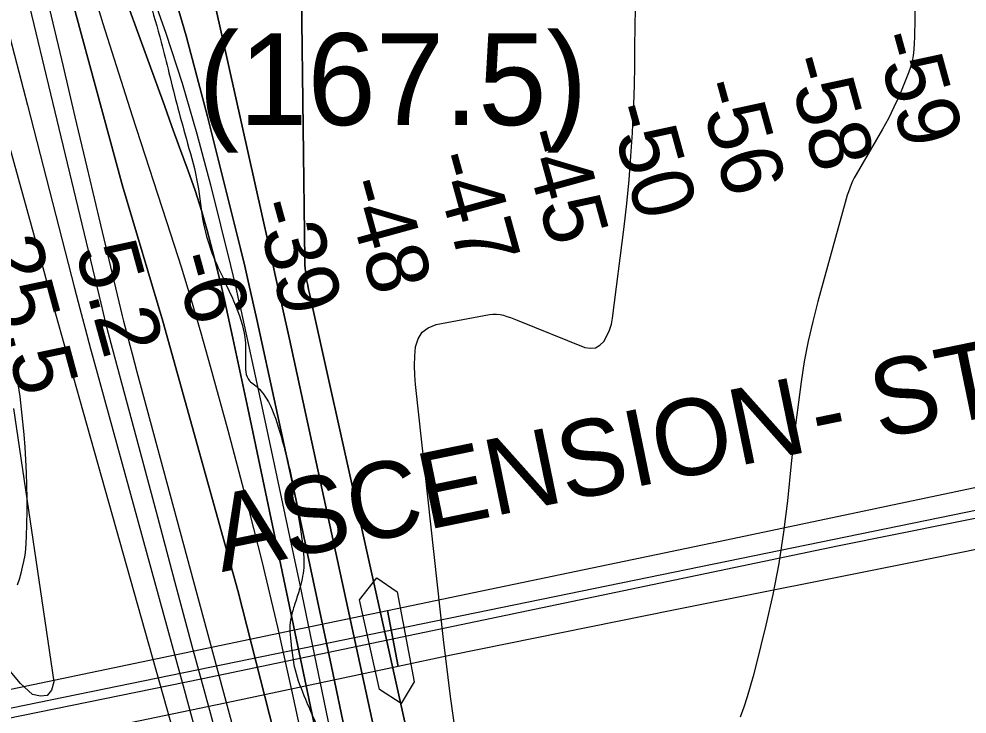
# Model space of a CAD drawing. Extents: x 3405885 to 3443815, y 558517 to 583997.
# Drawn here: x 3412709 to 3413741, y 581101 to 581858 of the extents above; entities that cross this region are included whole.
import ezdxf

# ---------------------------------------------------------------- set-up
doc = ezdxf.new("R2010")
doc.units = 0
for name, color, linetype in [('V-BRDG-IDEN', 7, 'Continuous'), ('V-BRDG-OTLN', 7, 'Continuous'), ('V-CHAN-DOCK', 7, 'Continuous'), ('V-CHAN-NAID', 7, 'Continuous'), ('V-RIVR-EDGE', 7, 'Continuous'), ('V-RIVR-RANG', 7, 'Continuous'), ('V-ROAD-CNTR', 7, 'Continuous'), ('V-TOPO-DPTH', 7, 'Continuous'), ('V-TOPO-MAJR', 7, 'Continuous'), ('V-TOPO-MINR', 7, 'Continuous'), ('V-TOPO-WATR', 7, 'Continuous')]:
    doc.layers.add(name, color=color, linetype=linetype)

msp = doc.modelspace()

# ---------------------------------------------------------------- linework, layer by layer
at = {"layer": 'V-BRDG-OTLN'}
for points in [[(3417680.4, 582119.8), (3417601.8, 582104.6), (3417266, 582031.9), (3417072.3, 581991.6), (3416368.4, 581849.5), (3415729.2, 581717.9), (3415183.5, 581606.5), (3414289.2, 581422.5), (3413599.8, 581283.7), (3412908.9, 581139.2), (3412266.4, 581008.4), (3412181.4, 580990.5), (3412075.2, 580969.3), (3411951.8, 580944.2), (3411795.1, 580912.3), (3411642, 580880.6), (3411498.5, 580851.2), (3411034.3, 580756.7), (3410912.4, 580731.2)], [(3411677.7, 580918.3), (3412408.2, 581067.1), (3413000.1, 581190.8), (3413110.1, 581213.7), (3413121.5, 581152.9), (3412941.9, 581114.8), (3412765.6, 581078.1), (3412568.7, 581037.8), (3412280.7, 580978.9), (3411914.4, 580903.8)]]:
    msp.add_lwpolyline(points, dxfattribs=at)
msp.add_lwpolyline([(3413110.1, 581213.7), (3413479, 581290.8), (3413890.7, 581377.6), (3413902.9, 581311.2), (3413681.3, 581266.1), (3413421.4, 581214.2), (3413179.2, 581165.2), (3413121.5, 581152.9)], close=True, dxfattribs=at)
at = {"layer": 'V-CHAN-DOCK'}
msp.add_lwpolyline([(3413101.3, 581127.9), (3413079.4, 581225.3), (3413098.4, 581249.5), (3413120.6, 581234), (3413139, 581136), (3413124.9, 581112.4)], close=True, dxfattribs=at)
at = {"layer": 'V-RIVR-EDGE'}
msp.add_spline([(3412820.9, 582098.3), (3412817.8, 582058), (3412815.6, 582029.5), (3412817.7, 582007.9), (3412825.7, 581980.1), (3412850.3, 581879.9), (3412863.7, 581832.7), (3412872, 581799.1), (3412892.3, 581722.3), (3412903.2, 581678.4), (3412909.6, 581634.8), (3412920.5, 581599), (3412934, 581569.3), (3412943.4, 581548.5), (3412954.7, 581511.2), (3412955.3, 581484.9), (3412959.7, 581464), (3412965.1, 581459.6), (3412977.9, 581445), (3412992.4, 581409.1), (3413006.5, 581353.1), (3413015.2, 581302.3), (3413018.7, 581260.3), (3413013.9, 581236.1), (3413008.8, 581220.1), (3413005.1, 581206.5), (3413003.6, 581194.5), (3413004.7, 581180.2), (3413009.3, 581149.1), (3413020.6, 581117.3), (3413042, 581073), (3413073, 581031.3), (3413081, 581018.1), (3413088.7, 580999.8), (3413094.4, 580977.9), (3413100.2, 580939.1), (3413102.7, 580912), (3413106.3, 580894.1), (3413113.5, 580861.9), (3413124.8, 580824.3), (3413140, 580781.4), (3413146.5, 580756.9), (3413148.7, 580740.1), (3413153.8, 580721.8), (3413161, 580692.6), (3413184.2, 580615.7), (3413194, 580582.5), (3413204.2, 580568.2), (3413207.8, 580561.6), (3413214, 580535.3), (3413232.1, 580461.7), (3413244, 580397.7), (3413253, 580345.1), (3413251.9, 580330.8), (3413256.4, 580258.4), (3413262.5, 580217.5), (3413264.6, 580175.4), (3413271.5, 580146.5), (3413278.7, 580117.3), (3413280.2, 580104.8), (3413276.4, 580060.6), (3413276.3, 580025.9), (3413275.6, 580012.4), (3413275.5, 580006.1), (3413277.7, 580003.2), (3413288, 580000.6), (3413298.6, 579998.4), (3413303.7, 579992.2), (3413305.5, 579985.2), (3413310.1, 579953.8), (3413314.5, 579931.1), (3413321, 579914.6), (3413327.2, 579894.5), (3413327.1, 579868.9), (3413323.4, 579842.6), (3413317.9, 579835.3), (3413316, 579824.7), (3413315.6, 579806.5), (3413320, 579780.1), (3413328, 579765.1), (3413335.6, 579758.2), (3413338.2, 579753.4), (3413338.9, 579747.5), (3413338.9, 579742.8), (3413335.5, 579730.7), (3413330.8, 579723.1), (3413327.8, 579714.3), (3413325.2, 579701.2), (3413326.7, 579689.5), (3413332.1, 579675.9), (3413338.3, 579668.2), (3413342.7, 579666.4), (3413352.6, 579666.7), (3413357.3, 579663.4), (3413365.3, 579652.4), (3413371.9, 579635.2), (3413374.8, 579618.4), (3413377.6, 579592.5), (3413379.4, 579557.4), (3413373.8, 579521.6), (3413375.2, 579501.1), (3413382.1, 579476.9), (3413395.1, 579440), (3413408.6, 579400.8), (3413417.6, 579358.8), (3413445.2, 579297.7), (3413449.9, 579271.7), (3413449.8, 579233.3), (3413439.5, 579191.3), (3413438.7, 579182.2), (3413439.8, 579172.7), (3413446, 579161.7), (3413464.9, 579134.6), (3413487.5, 579101.6), (3413497, 579074.9), (3413502.7, 579046.4), (3413506.7, 579018.2), (3413510.6, 578990.8), (3413518.6, 578952.4), (3413529.8, 578903.8), (3413538.1, 578871.6), (3413547.9, 578834.6), (3413558.4, 578787.4), (3413566.7, 578743.2), (3413574.6, 578699.3), (3413585.1, 578637.1), (3413595.2, 578577.2), (3413599.5, 578547.5), (3413610.7, 578516.1), (3413620.2, 578504), (3413626, 578499.2), (3413635.5, 578497), (3413635.9, 578494.4), (3413634.1, 578490.1), (3413632.2, 578487.1), (3413632.2, 578479.5), (3413633.2, 578455), (3413642.2, 578391), (3413644.3, 578359.2), (3413649, 578338.7), (3413656.3, 578322.2), (3413667.6, 578313.8), (3413676, 578309), (3413684.4, 578305.3), (3413688.8, 578300.2), (3413697.9, 578288.5), (3413702.2, 578272.4), (3413709.1, 578250.8), (3413714.9, 578233.2), (3413728.7, 578187.2), (3413734.8, 578151.3), (3413738.8, 578114.4), (3413740.5, 578084), (3413746.7, 578059.2), (3413750.7, 578043.4), (3413751.3, 578020), (3413747.6, 577990.8), (3413742, 577955), (3413736.9, 577934.5), (3413735.4, 577919.6), (3413733.5, 577904.2), (3413737.1, 577880.1), (3413741.4, 577864.7), (3413741.4, 577863.2), (3413750.2, 577865.8), (3413755, 577862.8), (3413760, 577845.7), (3413773.8, 577798.1), (3413781.8, 577765.2), (3413793, 577724.9), (3413797, 577700.4), (3413803.4, 577637.2), (3413804.4, 577613.8), (3413807.7, 577591.8), (3413815.3, 577561.1), (3413829.4, 577524.9), (3413841.8, 577493.8), (3413853.8, 577466), (3413863.2, 577445.5), (3413869.8, 577431.2), (3413869.8, 577426.1), (3413869.7, 577412.9), (3413868.9, 577389.5), (3413869.2, 577353), (3413871, 577339.8), (3413873.9, 577328.5), (3413883, 577306.5), (3413889.5, 577287.9), (3413905.1, 577244.3), (3413913.5, 577211), (3413925.4, 577161.3), (3413947.6, 577101.7), (3413958.8, 577073.5), (3413969, 577057.4), (3413973, 577043.8), (3413979.9, 577014.6), (3414002, 576930.8), (3414004.5, 576907.4), (3414006.3, 576897.2), (3414015, 576880.3), (3414024.5, 576858.8), (3414031.3, 576835.7), (3414040.8, 576799.5), (3414054.2, 576750.1), (3414062.5, 576713.9), (3414069.3, 576679.9), (3414074.4, 576668.5), (3414075.1, 576663.4), (3414103.1, 576586.2), (3414107.4, 576564.6), (3414115.4, 576529.2), (3414119, 576508), (3414142.2, 576433.7), (3414153.5, 576399.3), (3414159.6, 576378.5), (3414164.7, 576348.8), (3414174.1, 576303.8), (3414178, 576275), (3414184.1, 576248.3), (3414191.1, 576234), (3414204.1, 576202.1), (3414212.1, 576179.5), (3414243, 576089.5), (3414264.8, 576025.4), (3414269.5, 576005.7), (3414269.4, 575994.4), (3414267.6, 575989.1)], degree=3, dxfattribs=at)
at = {"layer": 'V-ROAD-CNTR'}
for points in [[(3409957, 580546.7), (3410940.8, 580747.1), (3417648.2, 582122.8)], [(3412707.2, 581241.7), (3412709.2, 581248), (3412711.1, 581254.4), (3412712.7, 581260.8), (3412714.1, 581267.3), (3412715.3, 581273.9), (3412716.3, 581280.4), (3412716.9, 581294.3), (3412717.3, 581308.2), (3412717.5, 581322.1), (3412717.5, 581336), (3412717.2, 581349.9), (3412716.8, 581363.8), (3412716.2, 581377.7), (3412715.3, 581391.6), (3412714.3, 581405.5), (3412713, 581419.3), (3412711.5, 581433.1), (3412709.9, 581446.9), (3412708, 581460.7)]]:
    msp.add_lwpolyline(points, dxfattribs=at)
at = {"layer": 'V-TOPO-DPTH'}
for points in [[(3412664.9, 582099.7), (3412797.7, 581548.5), (3412800.3, 581537.6), (3412803.1, 581526.7), (3412805.9, 581515.8), (3412808.7, 581505), (3412840.5, 581386.1), (3412859.4, 581315.8), (3412878.2, 581245.6), (3412897.1, 581175.3), (3412916, 581105.1), (3413003.6, 580780.3), (3413008.8, 580760.2), (3413013.8, 580740), (3413018.5, 580719.7), (3413022.9, 580699.3), (3413044.7, 580594.5), (3413059.4, 580521.5), (3413073.5, 580448.5), (3413086.5, 580375.3), (3413098.9, 580302), (3413146, 580011.8)], [(3412709.1, 582099.9), (3412741.1, 581971.9), (3412821.3, 581676.2), (3412865.2, 581528.8), (3412947.1, 581235.7), (3413065.1, 580772.3), (3413068.5, 580759.5), (3413070.2, 580745.9), (3413113.8, 580487.8), (3413186.9, 580114.7)], [(3413186.9, 580114.7), (3413113.8, 580487.8), (3413070.2, 580745.9), (3413068.5, 580759.5), (3413065.1, 580772.3), (3412947.1, 581235.7), (3412865.2, 581528.8), (3412821.3, 581676.2), (3412741.1, 581971.9), (3412709.1, 582099.9)], [(3413068.7, 581058.9), (3413049.1, 581152.8), (3413029.2, 581246.6), (3413009.1, 581340.4), (3412967.8, 581530.6), (3412963.5, 581550), (3412959.1, 581569.3), (3412954.5, 581588.7), (3412949.8, 581608), (3412914.1, 581751.8), (3412890.7, 581839.5), (3412865.3, 581926.6), (3412836.8, 582012.7), (3412806.3, 582098.2), (3412805.6, 582100.3)], [(3412805.6, 582100.3), (3412806.3, 582098.2), (3412836.8, 582012.7), (3412865.3, 581926.6), (3412890.7, 581839.5), (3412914.1, 581751.8), (3412949.8, 581608), (3412954.5, 581588.7), (3412959.1, 581569.3), (3412963.5, 581550), (3412967.8, 581530.6), (3413009.1, 581340.4), (3413029.2, 581246.6), (3413049.1, 581152.8), (3413068.7, 581058.9)], [(3412871.6, 582100.6), (3413021, 582101.1), (3413019.1, 582062.1), (3413017.1, 582003), (3413016.4, 581943.8), (3413016.5, 581884.6), (3413019.9, 581595.1), (3413020.1, 581590.5), (3413020.4, 581586), (3413020.9, 581581.4), (3413021.5, 581576.9), (3413022.3, 581572.4), (3413023.2, 581567.9), (3413024.1, 581563.4), (3413025.1, 581558.9), (3413187.4, 580829.4)], [(3413254.4, 580247.2), (3413244.5, 580301.5), (3413234.8, 580355.8), (3413163.6, 580759.6), (3413161.1, 580773.6), (3413158.5, 580787.6), (3413155.9, 580801.6), (3413153.2, 580815.6), (3413150.4, 580829.5), (3413147.6, 580843.5), (3413144.7, 580857.4), (3413141.7, 580871.3), (3413003.1, 581509.2), (3412995.7, 581543.2), (3412988.2, 581577.3), (3412980.7, 581611.3), (3412973.1, 581645.3), (3412871.6, 582100.6)], [(3413254.4, 580247.2), (3413244.5, 580301.5), (3413234.8, 580355.8), (3413163.6, 580759.6), (3413161.1, 580773.6), (3413158.5, 580787.6), (3413155.9, 580801.6), (3413153.2, 580815.6), (3413150.4, 580829.5), (3413147.6, 580843.5), (3413144.7, 580857.4), (3413141.7, 580871.3), (3413003.1, 581509.2), (3412995.7, 581543.2), (3412988.2, 581577.3), (3412980.7, 581611.3), (3412973.1, 581645.3), (3412871.6, 582100.6)], [(3413021, 582101.1), (3413019.1, 582062.1), (3413017.1, 582003), (3413016.4, 581943.8), (3413016.5, 581884.6), (3413019.9, 581595.1), (3413020.1, 581590.5), (3413020.4, 581586), (3413020.9, 581581.4), (3413021.5, 581576.9), (3413022.3, 581572.4), (3413023.2, 581567.9), (3413024.1, 581563.4), (3413025.1, 581558.9), (3413187.4, 580829.4)], [(3412806.9, 581929.2), (3412858.7, 581786.4), (3412867, 581763.6), (3412875.3, 581740.8), (3412883.6, 581718.1), (3412891.9, 581695.3), (3412893, 581692.4), (3412900.4, 581671), (3412907.4, 581649.4), (3412913.7, 581627.6), (3412919.6, 581605.6), (3412928.1, 581571), (3412929.3, 581566.2), (3412930.4, 581561.5), (3412931.5, 581556.7), (3412932.6, 581552), (3412941.5, 581510.5), (3412947, 581485), (3412952.5, 581459.5), (3412957.9, 581434), (3412963.3, 581408.5), (3413091.7, 580796.3)], [(3413091.7, 580796.3), (3412963.3, 581408.5), (3412957.9, 581434), (3412952.5, 581459.5), (3412947, 581485), (3412941.5, 581510.5), (3412932.6, 581552), (3412931.5, 581556.7), (3412930.4, 581561.5), (3412929.3, 581566.2), (3412928.1, 581571), (3412919.6, 581605.6), (3412913.7, 581627.6), (3412907.4, 581649.4), (3412900.4, 581671), (3412893, 581692.4), (3412891.9, 581695.3), (3412883.6, 581718.1), (3412875.3, 581740.8), (3412867, 581763.6), (3412858.7, 581786.4), (3412806.9, 581929.2)]]:
    msp.add_lwpolyline(points, dxfattribs=at)
at = {"layer": 'V-TOPO-MAJR'}
for points in [[(3413187.1, 581058.1), (3413178.6, 581120.1), (3413171, 581182.2), (3413140.5, 581460), (3413139.7, 581470.2), (3413139.3, 581480.4), (3413139.7, 581490.7), (3413140.4, 581500.9), (3413143.2, 581509.5), (3413147.6, 581516.7), (3413154.4, 581521.7), (3413162.9, 581525.2), (3413221, 581536.1), (3413224.8, 581536.5), (3413228.7, 581536.6), (3413232.5, 581536.1), (3413236.3, 581535.3), (3413240, 581534.1), (3413243.8, 581532.9), (3413247.5, 581531.5), (3413251.2, 581530.1), (3413325, 581500.3), (3413330.9, 581499.4), (3413336.4, 581499.9), (3413341.2, 581502.6), (3413345.6, 581506.7), (3413348.9, 581512.7), (3413351.7, 581518.9), (3413353.7, 581525.5), (3413355, 581532.2), (3413367.5, 581631.4), (3413370.5, 581657), (3413373, 581682.7), (3413375, 581708.4), (3413376.6, 581734.1), (3413377.1, 581743.5), (3413378, 581764.6), (3413378.8, 581785.7), (3413379.2, 581806.8), (3413379.4, 581827.9), (3413379.6, 581849), (3413379.9, 581870.1)], [(3412702.6, 581433.6), (3412746.6, 581136), (3412744, 581127.1), (3412739.5, 581121.3), (3412732.3, 581120.3), (3412723.3, 581122.4), (3412710.4, 581134.4), (3412699.2, 581147.7)]]:
    msp.add_lwpolyline(points, dxfattribs=at)
at = {"layer": 'V-TOPO-MINR'}
for points in [[(3412591.3, 582099.4), (3412669.7, 581821.2), (3412684.1, 581770), (3412698.4, 581718.7), (3412712.6, 581667.5), (3412726.7, 581616.2), (3412735.7, 581583.3), (3412745.3, 581548.4), (3412755, 581513.6), (3412764.7, 581478.8), (3412774.5, 581443.9), (3412968.7, 580755.4)], [(3412629.5, 582099.6), (3412632, 582090.6), (3412661.1, 581981.9), (3412689.7, 581872.9), (3412718, 581763.9), (3412769.3, 581564.7), (3412775, 581542.7), (3412780.8, 581520.7), (3412786.7, 581498.7), (3412792.7, 581476.7), (3412888.5, 581127.8), (3412906.5, 581062.2)], [(3412664.9, 582099.7), (3412797.7, 581548.5), (3412800.3, 581537.6), (3412803.1, 581526.7), (3412805.9, 581515.8), (3412808.7, 581505), (3412840.5, 581386.1), (3412859.4, 581315.8), (3412878.2, 581245.6), (3412897.1, 581175.3), (3412916, 581105.1), (3413003.6, 580780.3), (3413008.8, 580760.2), (3413013.8, 580740), (3413018.5, 580719.7), (3413022.9, 580699.3), (3413044.7, 580594.5), (3413059.4, 580521.5), (3413073.5, 580448.5), (3413086.5, 580375.3), (3413098.9, 580302), (3413146, 580011.8)], [(3412687.5, 582099.8), (3412743.8, 581861), (3412756.7, 581806.1), (3412769.7, 581751.2), (3412782.7, 581696.4), (3412795.7, 581641.5), (3412821, 581534.7), (3412821.4, 581533.3), (3412822.5, 581528.9), (3412826.8, 581512.5), (3412829.4, 581502.8), (3412832, 581493.1), (3412834.6, 581483.5), (3412837.2, 581473.8), (3413017.4, 580806), (3413025.2, 580776.1), (3413032.6, 580746.2), (3413039.5, 580716.1), (3413046.1, 580686), (3413091.7, 580468.9), (3413107.8, 580389.6), (3413123.1, 580310.3), (3413137.4, 580230.7)], [(3412729, 582100), (3412741.1, 582055), (3412769.6, 581953.7), (3412800.1, 581852.9), (3412831.8, 581752.6), (3412873.8, 581623.8), (3412885.2, 581588), (3412896.2, 581552.1), (3412906.8, 581516.1), (3412917, 581479.9), (3412936.1, 581410.1), (3412955.1, 581338.8), (3412973.2, 581267.4), (3412990.1, 581195.6), (3413006.3, 581123.6), (3413081, 580777.9)], [(3412774.3, 582100.2), (3412787.9, 582063.3), (3412807.5, 582010), (3412827.3, 581956.7), (3412847, 581903.4), (3412849.4, 581896.9), (3412868.5, 581842.6), (3412886.4, 581788), (3412902.4, 581732.8), (3412917.2, 581677.2), (3412939, 581589.5), (3412941.9, 581577.5), (3412944.8, 581565.4), (3412947.5, 581553.3), (3412950.2, 581541.3), (3412973, 581436), (3412986.9, 581371.3), (3413000.7, 581306.5), (3413014.4, 581241.7), (3413027.9, 581176.9), (3413102.8, 580815.4)], [(3412805.6, 582100.3), (3412806.3, 582098.2), (3412836.8, 582012.7), (3412865.3, 581926.6), (3412890.7, 581839.5), (3412914.1, 581751.8), (3412949.8, 581608), (3412954.5, 581588.7), (3412959.1, 581569.3), (3412963.5, 581550), (3412967.8, 581530.6), (3413009.1, 581340.4), (3413029.2, 581246.6), (3413049.1, 581152.8), (3413068.7, 581058.9)], [(3412871.6, 582100.6), (3412973.1, 581645.3), (3412980.7, 581611.3), (3412988.2, 581577.3), (3412995.7, 581543.2), (3413003.1, 581509.2), (3413141.7, 580871.3), (3413144.7, 580857.4), (3413147.6, 580843.5), (3413150.4, 580829.5), (3413153.2, 580815.6), (3413155.9, 580801.6), (3413158.5, 580787.6), (3413161.1, 580773.6), (3413163.6, 580759.6), (3413234.8, 580355.8), (3413244.5, 580301.5), (3413254.4, 580247.2)], [(3413187.4, 580829.4), (3413025.1, 581558.9), (3413024.1, 581563.4), (3413023.2, 581567.9), (3413022.3, 581572.4), (3413021.5, 581576.9), (3413020.9, 581581.4), (3413020.4, 581586), (3413020.1, 581590.5), (3413019.9, 581595.1), (3413016.5, 581884.6), (3413016.4, 581943.8), (3413017.1, 582003), (3413019.1, 582062.1), (3413021, 582101.1)], [(3413684.1, 582021.8), (3413684, 581851.6), (3413683.9, 581844.9), (3413683.8, 581838.2), (3413683.4, 581831.5), (3413683.1, 581824.8), (3413682.3, 581818.2), (3413681.1, 581811.7), (3413679.4, 581805.3), (3413677.2, 581799.1), (3413672.2, 581786.4), (3413667, 581774), (3413661.4, 581761.7), (3413655.3, 581749.7), (3413648.8, 581737.9), (3413620.1, 581688.4), (3413618.2, 581684.9), (3413616.3, 581681.2), (3413614.7, 581677.5), (3413613.2, 581673.7), (3413611.8, 581669.8), (3413610.5, 581666), (3413609.3, 581662.1), (3413608.1, 581658.1), (3413578.4, 581550.3), (3413572.9, 581528.6), (3413567.9, 581506.9), (3413563.8, 581484.9), (3413560.3, 581462.8), (3413557.3, 581440.7), (3413554.5, 581418.5), (3413551.9, 581396.2), (3413549.6, 581374), (3413545.5, 581333.1), (3413541.3, 581298.9), (3413536.2, 581265), (3413529.6, 581231.2), (3413522, 581197.7), (3413511, 581153.6), (3413508.1, 581142.3), (3413504.9, 581131), (3413501.4, 581119.7), (3413497.8, 581108.6), (3413494, 581097.5)], [(3412806.9, 581929.2), (3412858.7, 581786.4), (3412867, 581763.6), (3412875.3, 581740.8), (3412883.6, 581718.1), (3412891.9, 581695.3), (3412893, 581692.4), (3412900.4, 581671), (3412907.4, 581649.4), (3412913.7, 581627.6), (3412919.6, 581605.6), (3412928.1, 581571), (3412929.3, 581566.2), (3412930.4, 581561.5), (3412931.5, 581556.7), (3412932.6, 581552), (3412941.5, 581510.5), (3412947, 581485), (3412952.5, 581459.5), (3412957.9, 581434), (3412963.3, 581408.5), (3413091.7, 580796.3)]]:
    msp.add_lwpolyline(points, dxfattribs=at)
at = {"layer": 'V-TOPO-WATR'}
msp.add_lwpolyline([(3413186.9, 580114.7), (3413113.8, 580487.8), (3413070.2, 580745.9), (3413068.5, 580759.5), (3413065.1, 580772.3), (3412947.1, 581235.7), (3412865.2, 581528.8), (3412821.3, 581676.2), (3412741.1, 581971.9), (3412709.1, 582099.9)], dxfattribs=at)

# ---------------------------------------------------------------- texts
at = {"layer": 'V-BRDG-IDEN'}
for s, p in [('- ST. JAMES HWY BRIDGE', (3413578.8, 581386.8)), ('ASCENSION', (3412929.6, 581255.5))]:
    msp.add_text(s, height=83, rotation=11.6165, dxfattribs=at).set_placement(p)
at = {"layer": 'V-CHAN-NAID'}
msp.add_text('(167.5)', height=100, dxfattribs=at).set_placement((3412903.9, 581742.4))
at = {"layer": 'V-RIVR-RANG'}
for s, rotation, p in [('-59', 285.4091, (3413639.2, 581838)), ('-58', 285.4091, (3413542.6, 581812.4)), ('-56', 285.4091, (3413446.2, 581785.6)), ('-50', 285.4091, (3413349.6, 581760)), ('-45', 285.4091, (3413253.4, 581732.4)), ('-47', 285.4091, (3413156.7, 581707.1)), ('-48', 285.4091, (3413060.8, 581678.7)), ('-39', 285.4091, (3412963.5, 581655.2)), ('25.5', 285.1283, (3412664.8, 581612.1)), ('5.2', 285.4091, (3412769.6, 581606.1)), ('-6', 285.4091, (3412875.7, 581597.6))]:
    msp.add_text(s, height=67, rotation=rotation, dxfattribs=at).set_placement(p)

doc.saveas('drawing.dxf')
